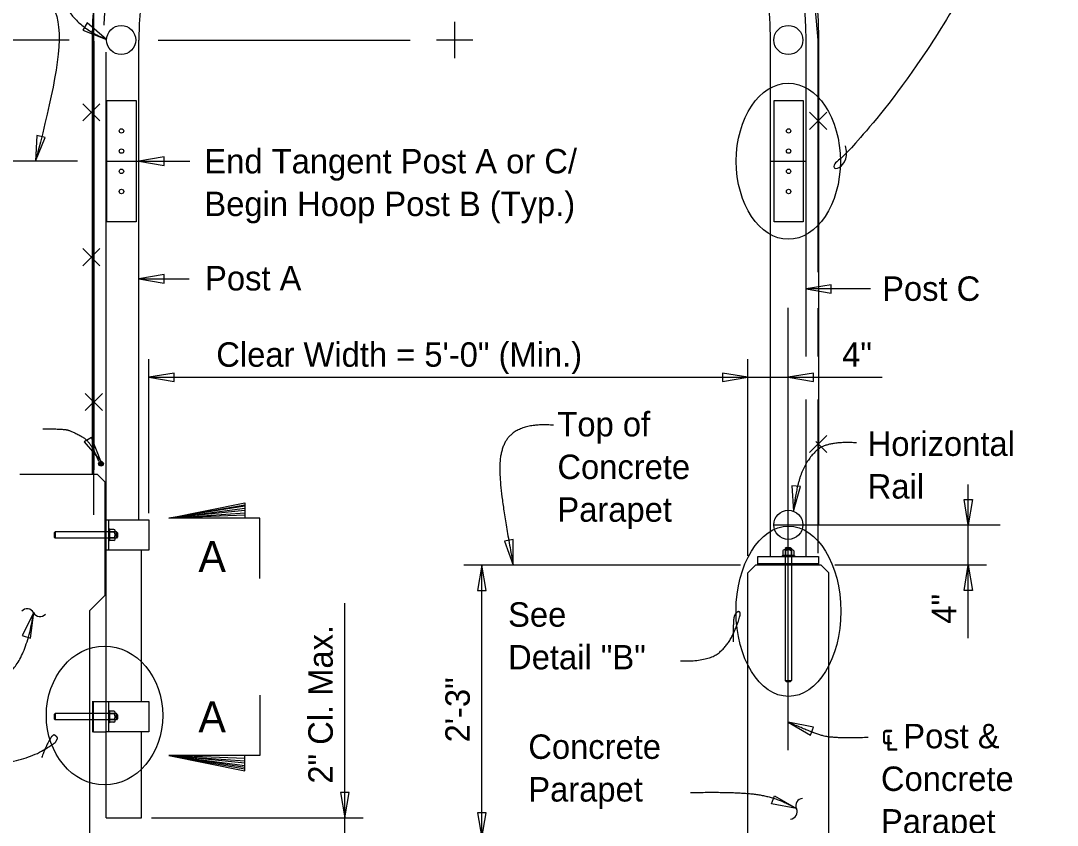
# Model space of a CAD drawing. Extents: x 110341.7 to 110413.5, y 110387.3 to 110417.8.
# Drawn here: x 110373.78 to 110382.32, y 110403.95 to 110410.59 of the extents above; entities that cross this region are included whole.
import ezdxf

# ---------------------------------------------------------------- set-up
doc = ezdxf.new("R2010")
doc.units = 0
for name, color, linetype in [('AdhocPoint_dp', 7, 'Continuous'), ('Border', 7, 'Continuous'), ('CL_Major', 7, 'Continuous'), ('CL_Minor', 7, 'Continuous'), ('Patterning', 7, 'Continuous'), ('PlotBorder_dp', 7, 'Continuous'), ('SheetBorder_dp', 7, 'Continuous'), ('TextMisc', 7, 'Continuous'), ('TrafBarrierConc', 7, 'Continuous')]:
    doc.layers.add(name, color=color, linetype=linetype)

msp = doc.modelspace()

# ---------------------------------------------------------------- linework, layer by layer
at = {"layer": 'AdhocPoint_dp'}
for p, q in [((110374.3782, 110412.5102), (110374.3782, 110406.5102)), ((110374.7532, 110406.4685), (110374.7532, 110410.4268)), ((110379.9615, 110406.1664), (110379.9615, 110410.4268)), ((110380.2532, 110407.8143), (110380.2532, 110410.4268)), ((110374.4823, 110406.4685), (110374.4823, 110410.3274)), ((110374.4823, 110409.4268), (110374.7532, 110409.4268)), ((110379.9615, 110409.4268), (110380.2532, 110409.4268)), ((110380.2532, 110406.1664), (110380.2532, 110407.4599)), ((110374.4823, 110406.2185), (110374.4823, 110406.4685)), ((110374.4823, 110406.4685), (110374.8365, 110406.4685)), ((110374.5031, 110406.4685), (110374.5031, 110406.2185)), ((110374.8365, 110406.4685), (110374.8365, 110406.2185)), ((110374.5102, 110406.3932), (110374.5031, 110406.3932)), ((110374.5102, 110406.3932), (110374.5102, 110406.2937)), ((110374.5478, 110406.3889), (110374.5102, 110406.3889)), ((110374.5102, 110406.2981), (110374.5102, 110406.3889)), ((110374.5481, 110406.3662), (110374.5102, 110406.3662)), ((110374.5481, 110406.3208), (110374.5102, 110406.3208)), ((110374.5565, 110406.3094), (110374.5565, 110406.3775)), ((110374.5678, 110406.3692), (110374.5565, 110406.3692)), ((110374.5678, 110406.3692), (110374.5678, 110406.3177)), ((110374.5775, 110406.3596), (110374.5678, 110406.3692)), ((110374.5775, 110406.329), (110374.5678, 110406.3177)), ((110374.5775, 110406.3596), (110374.5775, 110406.329)), ((110374.5102, 110406.2937), (110374.5031, 110406.2937)), ((110374.5478, 110406.2981), (110374.5102, 110406.2981)), ((110374.5678, 110406.3177), (110374.5565, 110406.3177)), ((110380.0912, 110406.2407), (110380.0816, 110406.231)), ((110380.0912, 110406.2407), (110380.1218, 110406.2407)), ((110380.1218, 110406.2407), (110380.1331, 110406.231)), ((110374.4823, 110404.0102), (110374.4823, 110406.2185)), ((110374.8365, 110406.2185), (110374.4823, 110406.2185)), ((110374.774, 110404.9685), (110374.774, 110406.2185)), ((110380.0577, 110406.1734), (110380.0577, 110406.1663)), ((110380.0577, 110406.1734), (110380.1571, 110406.1734)), ((110380.0619, 110406.211), (110380.0619, 110406.1734)), ((110380.1527, 110406.1734), (110380.0619, 110406.1734)), ((110380.1414, 110406.2197), (110380.0733, 110406.2197)), ((110380.0816, 110406.231), (110380.0816, 110406.2197)), ((110380.0816, 110406.231), (110380.1331, 110406.231)), ((110380.0846, 110406.2113), (110380.0846, 110406.1734)), ((110380.13, 110406.2113), (110380.13, 110406.1734)), ((110380.1331, 110406.231), (110380.1331, 110406.2197)), ((110380.1527, 110406.211), (110380.1527, 110406.1734)), ((110380.1571, 110406.1734), (110380.1571, 110406.1663)), ((110379.9875, 110406.1039), (110380.2271, 110406.1039)), ((110374.3781, 110404.7185), (110374.3781, 110404.9685)), ((110374.3781, 110404.9685), (110374.4823, 110404.9685)), ((110374.4823, 110404.9685), (110374.8365, 110404.9685)), ((110374.5031, 110404.9685), (110374.5031, 110404.7185)), ((110374.8365, 110404.9685), (110374.8365, 110404.7185)), ((110374.5102, 110404.8931), (110374.5031, 110404.8931)), ((110374.5102, 110404.8931), (110374.5102, 110404.7937)), ((110374.5478, 110404.8889), (110374.5102, 110404.8889)), ((110374.5102, 110404.7981), (110374.5102, 110404.8889)), ((110374.5565, 110404.8094), (110374.5565, 110404.8775)), ((110374.5678, 110404.8692), (110374.5565, 110404.8692)), ((110374.5678, 110404.8692), (110374.5678, 110404.8177)), ((110374.5775, 110404.8595), (110374.5678, 110404.8692)), ((110374.5102, 110404.7937), (110374.5031, 110404.7937)), ((110374.5481, 110404.8661), (110374.5102, 110404.8661)), ((110374.5481, 110404.8208), (110374.5102, 110404.8208)), ((110374.5478, 110404.7981), (110374.5102, 110404.7981)), ((110374.5678, 110404.8177), (110374.5565, 110404.8177)), ((110374.5775, 110404.829), (110374.5678, 110404.8177)), ((110374.5775, 110404.8595), (110374.5775, 110404.829)), ((110374.3781, 110404.7185), (110374.4823, 110404.7185)), ((110374.8365, 110404.7185), (110374.4823, 110404.7185)), ((110374.774, 110404.0102), (110374.774, 110404.7185))]:
    msp.add_line(p, q, dxfattribs=at)
msp.add_lwpolyline([(110379.8573, 110406.1664), (110380.3573, 110406.1664), (110380.3573, 110406.1039), (110379.8573, 110406.1039)], close=True, dxfattribs=at)
msp.add_lwpolyline([(110374.4823, 110404.0102), (110374.774, 110404.0102)], dxfattribs=at)
for centre, radius in [((110374.6073, 110410.4268), 0.1198), ((110380.1073, 110410.4268), 0.1198), ((110374.6097, 110409.6768), 0.0182), ((110380.1097, 110409.6768), 0.0182), ((110374.6097, 110409.5102), 0.0182), ((110380.1097, 110409.5102), 0.0182), ((110374.6097, 110409.3435), 0.0182), ((110380.1097, 110409.3435), 0.0182), ((110374.6097, 110409.1768), 0.0182), ((110380.1097, 110409.1768), 0.0182), ((110374.4406, 110406.9312), 0.0197), ((110374.4406, 110406.9312), 0.0172), ((110374.4406, 110406.9312), 0.0147), ((110374.4406, 110406.9312), 0.0122), ((110374.4406, 110406.9312), 0.00975), ((110374.4406, 110406.9312), 0.00725), ((110374.4406, 110406.9312), 0.00475), ((110374.4406, 110406.9312), 0.00225), ((110380.1073, 110406.4268), 0.1198)]:
    msp.add_circle(centre, radius, dxfattribs=at)
for centre, radius, start, end in [((110377.3573, 110410.4268), 2.8958, 0, 133.8265), ((110377.3573, 110410.4268), 2.6042, 0, 180), ((110377.3573, 110410.4268), 2.8958, 137.3283, 177.59625), ((110374.5448, 110406.3775), 0.0118, 286.59863, 74.70054), ((110374.5448, 110406.3095), 0.0118, 285.15064, 73.50417), ((110374.5219, 110406.3435), 0.0347, 319.20147, 40.79853), ((110380.0733, 110406.208), 0.0118, 16.59863, 164.70054), ((110380.1073, 110406.185), 0.0347, 49.20147, 130.79853), ((110380.1413, 110406.208), 0.0118, 15.15064, 163.50417), ((110374.5448, 110404.8774), 0.0118, 286.59863, 74.70054), ((110374.5448, 110404.8094), 0.0118, 285.15064, 73.50417), ((110374.5219, 110404.8434), 0.0347, 319.20147, 40.79853)]:
    msp.add_arc(centre, radius, start, end, dxfattribs=at)
at = {"layer": 'Border'}
for p, q in [((110377.3573, 110410.2768), (110377.3573, 110410.5768)), ((110374.1798, 110410.4268), (110369.4395, 110410.4268)), ((110374.911, 110410.4268), (110376.9889, 110410.4268)), ((110377.5073, 110410.4268), (110377.2073, 110410.4268)), ((110374.7531, 110409.4268), (110375.1736, 110409.4268)), ((110374.7531, 110408.4569), (110375.169, 110408.4569)), ((110380.7856, 110408.373), (110380.2532, 110408.373)), ((110374.8365, 110406.5233), (110374.8365, 110407.7942)), ((110379.774, 110406.1711), (110379.774, 110407.7942)), ((110374.8365, 110407.6442), (110380.882, 110407.6442)), ((110381.5911, 110406.4268), (110381.5911, 110406.7601)), ((110375.0009, 110406.483), (110375.6259, 110406.593)), ((110375.6259, 110406.5796), (110375.0009, 110406.483)), ((110375.0009, 110406.483), (110375.6259, 110406.563)), ((110375.6259, 110406.5446), (110375.0009, 110406.483)), ((110375.0009, 110406.483), (110375.6259, 110406.5263)), ((110375.6259, 110406.5063), (110375.0009, 110406.483)), ((110381.5911, 110406.0935), (110381.5911, 110406.4268)), ((110374.511, 110406.3434), (110374.5103, 110406.3434)), ((110380.1073, 110406.1741), (110380.1073, 110406.1734)), ((110379.7138, 110406.0935), (110377.4312, 110406.0935)), ((110377.5812, 110403.8637), (110377.5812, 110406.0935)), ((110381.7411, 110406.0935), (110380.4908, 110406.0935)), ((110381.5911, 110405.4915), (110381.5911, 110406.0935)), ((110376.4515, 110403.3484), (110376.4515, 110405.7809)), ((110374.511, 110404.8434), (110374.5103, 110404.8434)), ((110375.6259, 110404.4991), (110375.0009, 110404.5224)), ((110375.0009, 110404.5224), (110375.6259, 110404.4791)), ((110375.6259, 110404.4607), (110375.0009, 110404.5224)), ((110375.0009, 110404.5224), (110375.6259, 110404.4424)), ((110375.6259, 110404.4257), (110375.0009, 110404.5224)), ((110375.0009, 110404.5224), (110375.6259, 110404.4124)), ((110374.8586, 110404.0102), (110376.6015, 110404.0102))]:
    msp.add_line(p, q, dxfattribs=at)
for points in [[(110374.4876, 110410.4307), (110374.327, 110410.5679), (110374.2908, 110410.5073)], [(110373.902, 110409.4268), (110373.9799, 110409.6231), (110373.9109, 110409.6379)], [(110374.7531, 110409.4268), (110374.9614, 110409.3915), (110374.9614, 110409.4621)], [(110374.7531, 110408.4568), (110374.9614, 110408.4215), (110374.9614, 110408.4921)], [(110380.2531, 110408.373), (110380.4614, 110408.3377), (110380.4614, 110408.4082)], [(110374.8365, 110407.6442), (110375.0447, 110407.6089), (110375.0447, 110407.6794)], [(110379.774, 110407.6441), (110379.5658, 110407.6794), (110379.5658, 110407.6088)], [(110380.1073, 110407.6441), (110380.3155, 110407.6088), (110380.3155, 110407.6794)], [(110374.4406, 110406.9509), (110374.3622, 110407.1471), (110374.302, 110407.1103)], [(110380.1501, 110406.5387), (110380.2066, 110406.7422), (110380.1364, 110406.7494)], [(110381.5911, 110406.4268), (110381.5558, 110406.635), (110381.6264, 110406.635)], [(110377.8402, 110406.0935), (110377.8376, 110406.3047), (110377.7682, 110406.2921)], [(110377.5812, 110406.0935), (110377.5459, 110405.8852), (110377.6165, 110405.8852)], [(110381.5911, 110406.0935), (110381.6264, 110405.8852), (110381.5558, 110405.8852)], [(110373.8861, 110405.7022), (110373.792, 110405.5132), (110373.8595, 110405.4927)], [(110380.1073, 110404.798), (110380.29, 110404.6919), (110380.3147, 110404.758)], [(110376.4515, 110404.0102), (110376.4867, 110404.2184), (110376.4162, 110404.2184)], [(110380.175, 110404.0853), (110379.9675, 110404.1249), (110379.9922, 110404.191)], [(110377.5812, 110403.8435), (110377.6165, 110404.0517), (110377.5459, 110404.0517)]]:
    msp.add_lwpolyline(points, close=True, dxfattribs=at)
for points in [[(110375.7509, 110405.983), (110375.7509, 110406.483), (110375.0009, 110406.483), (110375.6259, 110406.608), (110375.6259, 110406.483)], [(110375.7509, 110405.0224), (110375.7509, 110404.5224), (110375.0009, 110404.5224), (110375.6259, 110404.3974), (110375.6259, 110404.5224)]]:
    msp.add_lwpolyline(points, dxfattribs=at)
for centre, start, end in [((110373.8324, 110405.675), 27.32823, 139.05545), ((110373.9383, 110405.7298), 207.32823, 319.05545), ((110380.2286, 110404.1102), 93.65656, 205.38378), ((110380.1209, 110404.0591), 273.65656, 25.38378)]:
    msp.add_arc(centre, 0.0596, start, end, dxfattribs=at)
for centre, major_axis, ratio in [((110380.1073, 110409.4268), (0, 0.644), 0.666248), ((110380.1086, 110405.7133), (0, 0.7024), 0.61552), ((110374.47, 110404.8534), (0, -0.5725), 0.837861)]:
    msp.add_ellipse(centre, major_axis=major_axis, ratio=ratio, dxfattribs=at)
for points, degree in [([(110381.9663, 110412.9512), (110382.3246, 110412.9586), (110382.0241, 110411.6349), (110381.2192, 110410.2347), (110380.6224, 110409.5191), (110380.5061, 110409.4208), (110380.4818, 110409.4045), (110380.4812, 110409.3325), (110380.6106, 110409.4328), (110380.5792, 110409.5527)], 3), ([(110374.1699, 110412.3366), (110374.4128, 110412.3386), (110374.5535, 110412.3207), (110374.4128, 110411.7235), (110373.9479, 110410.6564), (110374.4876, 110410.4307)], 2), ([(110373.7953, 110410.8908), (110373.8997, 110410.8718), (110374.2308, 110410.7056), (110374.0051, 110409.8431), (110373.9021, 110409.4268)], 3), ([(110373.96, 110407.2191), (110374.1298, 110407.2191), (110374.1996, 110407.2003), (110374.3628, 110407.1121), (110374.4199, 110406.951)], 2), ([(110378.1706, 110407.2484), (110377.9464, 110407.2661), (110377.7281, 110407.1008), (110377.7281, 110406.6815), (110377.8402, 110406.0935)], 2), ([(110380.6697, 110407.1032), (110380.4241, 110407.1178), (110380.2574, 110406.9627), (110380.1697, 110406.7286), (110380.1501, 110406.5387)], 2), ([(110372.9834, 110405.1588), (110373.3731, 110405.1576), (110373.8006, 110405.1877), (110373.8861, 110405.7022)], 2), ([(110379.2185, 110405.3035), (110379.4451, 110405.2995), (110379.6156, 110405.4344), (110379.7107, 110405.6646), (110379.7107, 110405.7163), (110379.6735, 110405.7015), (110379.6512, 110405.6487), (110379.6527, 110405.4619)], 2), ([(110380.7649, 110404.6724), (110380.4749, 110404.6595), (110380.2845, 110404.7201), (110380.1073, 110404.7981)], 2), ([(110372.8541, 110404.4148), (110373.3, 110404.4024), (110373.8367, 110404.4923), (110374.0618, 110404.6246), (110374.0725, 110404.6465), (110374.0886, 110404.6725), (110374.0295, 110404.7102), (110373.9514, 110404.506)], 2), ([(110379.2997, 110404.2176), (110379.6382, 110404.2259), (110380.0099, 110404.1845), (110380.175, 110404.0853)], 2)]:
    msp.add_open_spline(points, degree=degree, dxfattribs=at)
at = {"layer": 'CL_Major'}
for p, q in [((110374.2482, 110409.4268), (110370.4395, 110409.4268)), ((110380.1073, 110404.5685), (110380.1073, 110408.2179))]:
    msp.add_line(p, q, dxfattribs=at)
at = {"layer": 'CL_Minor'}
msp.add_line((110379.9875, 110406.4268), (110381.8544, 110406.4268), dxfattribs=at)
at = {"layer": 'Patterning'}
for p, q in [((110374.3682, 110410.4324), (110374.3682, 110406.849)), ((110380.3598, 110406.4323), (110380.3598, 110410.4324)), ((110374.4321, 110409.9002), (110374.2907, 110409.759)), ((110374.2907, 110409.9002), (110374.4321, 110409.759)), ((110380.2826, 110409.6895), (110380.424, 110409.8308)), ((110380.424, 110409.6895), (110380.2826, 110409.8308)), ((110374.4321, 110408.7058), (110374.2907, 110408.5645)), ((110374.2907, 110408.7058), (110374.4321, 110408.5645)), ((110374.4529, 110407.5114), (110374.3115, 110407.3701)), ((110374.3115, 110407.5114), (110374.4529, 110407.3701)), ((110380.2826, 110407.0228), (110380.424, 110407.1641)), ((110380.424, 110407.0228), (110380.3337, 110407.113)), ((110374.4719, 110406.4685), (110374.4823, 110406.4685)), ((110374.4755, 110406.4685), (110374.4755, 110406.2185)), ((110374.4788, 110406.4685), (110374.4788, 110406.2185)), ((110374.5629, 110406.3547), (110374.5629, 110406.3339)), ((110374.5726, 110406.3547), (110374.5726, 110406.3339)), ((110380.0961, 110406.2358), (110380.1169, 110406.2358)), ((110374.4823, 110406.2185), (110374.4719, 110406.2185)), ((110380.0961, 110406.2261), (110380.1169, 110406.2261)), ((110379.8573, 110406.1004), (110380.3573, 110406.1004)), ((110379.8573, 110406.0969), (110380.3573, 110406.0969)), ((110374.3677, 110404.9685), (110374.3781, 110404.9685)), ((110374.3713, 110404.9685), (110374.3713, 110404.7185)), ((110374.3746, 110404.9685), (110374.3746, 110404.7185)), ((110374.5629, 110404.8546), (110374.5629, 110404.8339)), ((110374.5726, 110404.8546), (110374.5726, 110404.8339)), ((110374.3781, 110404.7185), (110374.3677, 110404.7185))]:
    msp.add_line(p, q, dxfattribs=at)
for points in [[(110380.3532, 110408.5115), (110380.3532, 110410.4269), (110380.3053, 110410.9604), (110380.1631, 110411.477), (110379.9312, 110411.9599), (110379.617, 110412.3939), (110379.2305, 110412.7649), (110378.7841, 110413.0611), (110378.2921, 110413.2732), (110377.7702, 110413.3941), (110377.2351, 110413.4202), (110376.7039, 110413.3505), (110376.1936, 110413.1874), (110375.7205, 110412.936), (110375.2998, 110412.6043), (110375.2699, 110412.5705)], [(110374.3823, 110410.4179), (110374.3823, 110406.8801)], [(110380.3532, 110407.8143), (110380.3532, 110408.2148)], [(110380.3532, 110406.1941), (110380.3532, 110407.4599)]]:
    msp.add_lwpolyline(points, dxfattribs=at)
msp.add_lwpolyline([(110379.8573, 110406.1039), (110380.3573, 110406.1039), (110380.3573, 110406.0935), (110379.8573, 110406.0935)], close=True, dxfattribs=at)
msp.add_arc((110377.364, 110410.4324), 2.9958, 0, 180, dxfattribs=at)
at = {"layer": 'PlotBorder_dp'}
for p, q in [((110379.8365, 110406.0934), (110379.774, 110406.0301)), ((110380.3781, 110406.0934), (110379.8365, 110406.0934)), ((110380.3781, 110406.0934), (110380.4407, 110406.0301)), ((110379.774, 110403.8435), (110379.774, 110406.0301)), ((110380.4407, 110403.8435), (110380.4407, 110406.0301))]:
    msp.add_line(p, q, dxfattribs=at)
at = {"layer": 'TextMisc'}
for p, q in [((110374.0633, 110406.3695), (110374.0552, 110406.3613)), ((110374.0552, 110406.3613), (110374.0552, 110406.3256)), ((110374.0633, 110406.3174), (110374.0552, 110406.3256)), ((110374.5565, 110406.3695), (110374.0633, 110406.3695)), ((110374.0633, 110406.3695), (110374.0633, 110406.3174)), ((110374.5565, 110406.3174), (110374.0633, 110406.3174)), ((110380.0813, 110406.2197), (110380.0813, 110405.1432)), ((110380.1334, 110406.2197), (110380.1334, 110405.1432)), ((110380.0813, 110405.1432), (110380.1334, 110405.1432)), ((110380.0813, 110405.1432), (110380.0895, 110405.1351)), ((110380.0895, 110405.1351), (110380.1252, 110405.1351)), ((110380.1334, 110405.1432), (110380.1252, 110405.1351)), ((110374.0633, 110404.8695), (110374.0552, 110404.8613)), ((110374.5565, 110404.8695), (110374.0633, 110404.8695)), ((110374.0633, 110404.8695), (110374.0633, 110404.8174)), ((110374.0552, 110404.8613), (110374.0552, 110404.8256)), ((110374.0633, 110404.8174), (110374.0552, 110404.8256)), ((110374.5565, 110404.8174), (110374.0633, 110404.8174))]:
    msp.add_line(p, q, dxfattribs=at)
for points in [[(110374.4899, 110409.9268), (110374.7295, 110409.9268), (110374.7295, 110408.9268), (110374.4899, 110408.9268)], [(110379.9899, 110409.9268), (110380.2295, 110409.9268), (110380.2295, 110408.9268), (110379.9899, 110408.9268)]]:
    msp.add_lwpolyline(points, close=True, dxfattribs=at)
at = {"layer": 'TrafBarrierConc'}
for p, q in [((110373.7704, 110406.8434), (110374.4094, 110406.8435)), ((110374.4094, 110406.8434), (110374.4719, 110406.7809)), ((110374.4719, 110406.7809), (110374.4719, 110405.8434)), ((110374.4719, 110405.8434), (110374.3469, 110405.7184)), ((110374.3469, 110405.7184), (110374.3469, 110403.8435))]:
    msp.add_line(p, q, dxfattribs=at)

# ---------------------------------------------------------------- texts
at = {"layer": 'Border'}
for s, p in [('End Tangent Post A or C/', (110375.2934, 110409.3264)), ('Begin Hoop Post B (Typ.)', (110375.2934, 110408.9744)), ('Top of ', (110378.2037, 110407.1564)), ('Horizontal ', (110380.7618, 110406.9954)), ('Concrete', (110378.2037, 110406.8044)), ('Rail', (110380.7618, 110406.6434)), ('Parapet', (110378.2037, 110406.4524)), ('See ', (110377.7972, 110405.5862)), ('Detail "B"', (110377.7972, 110405.2342)), ('℄ Post &', (110380.871, 110404.5832)), ('Concrete', (110377.9637, 110404.4957)), ('Concrete', (110380.871, 110404.2312)), ('Parapet', (110377.9637, 110404.1437)), ('Parapet', (110380.871, 110403.8792))]:
    msp.add_text(s, height=0.2016, dxfattribs=at).set_placement(p)
at = {"layer": 'SheetBorder_dp'}
for s, height, p in [('Post A', 0.2016, (110375.2991, 110408.3606)), ('Post C', 0.2016, (110380.8809, 110408.2748)), ('Clear Width = 5\'-0" (Min.)', 0.2016, (110375.3913, 110407.731)), ('4"', 0.2016, (110380.551, 110407.731)), ('A', 0.256, (110375.2432, 110406.0365)), ('A', 0.256, (110375.2432, 110404.7134))]:
    msp.add_text(s, height=height, dxfattribs=at).set_placement(p)
for s, p in [('4"', (110381.4914, 110405.6113)), ('2" Cl. Max.', (110376.3517, 110404.2913)), ('2\'-3"', (110377.4815, 110404.6317))]:
    msp.add_text(s, height=0.2016, rotation=90, dxfattribs=at).set_placement(p)

doc.saveas('drawing.dxf')
